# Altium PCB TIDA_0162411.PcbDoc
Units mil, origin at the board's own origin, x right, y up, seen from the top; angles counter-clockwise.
Board outline 1285 x 1080 mil, 2 copper layers (Top Layer, Bottom Layer), stack 4.4 mil thick; 24 components, 21 nets, 89 pads, 29 vias.
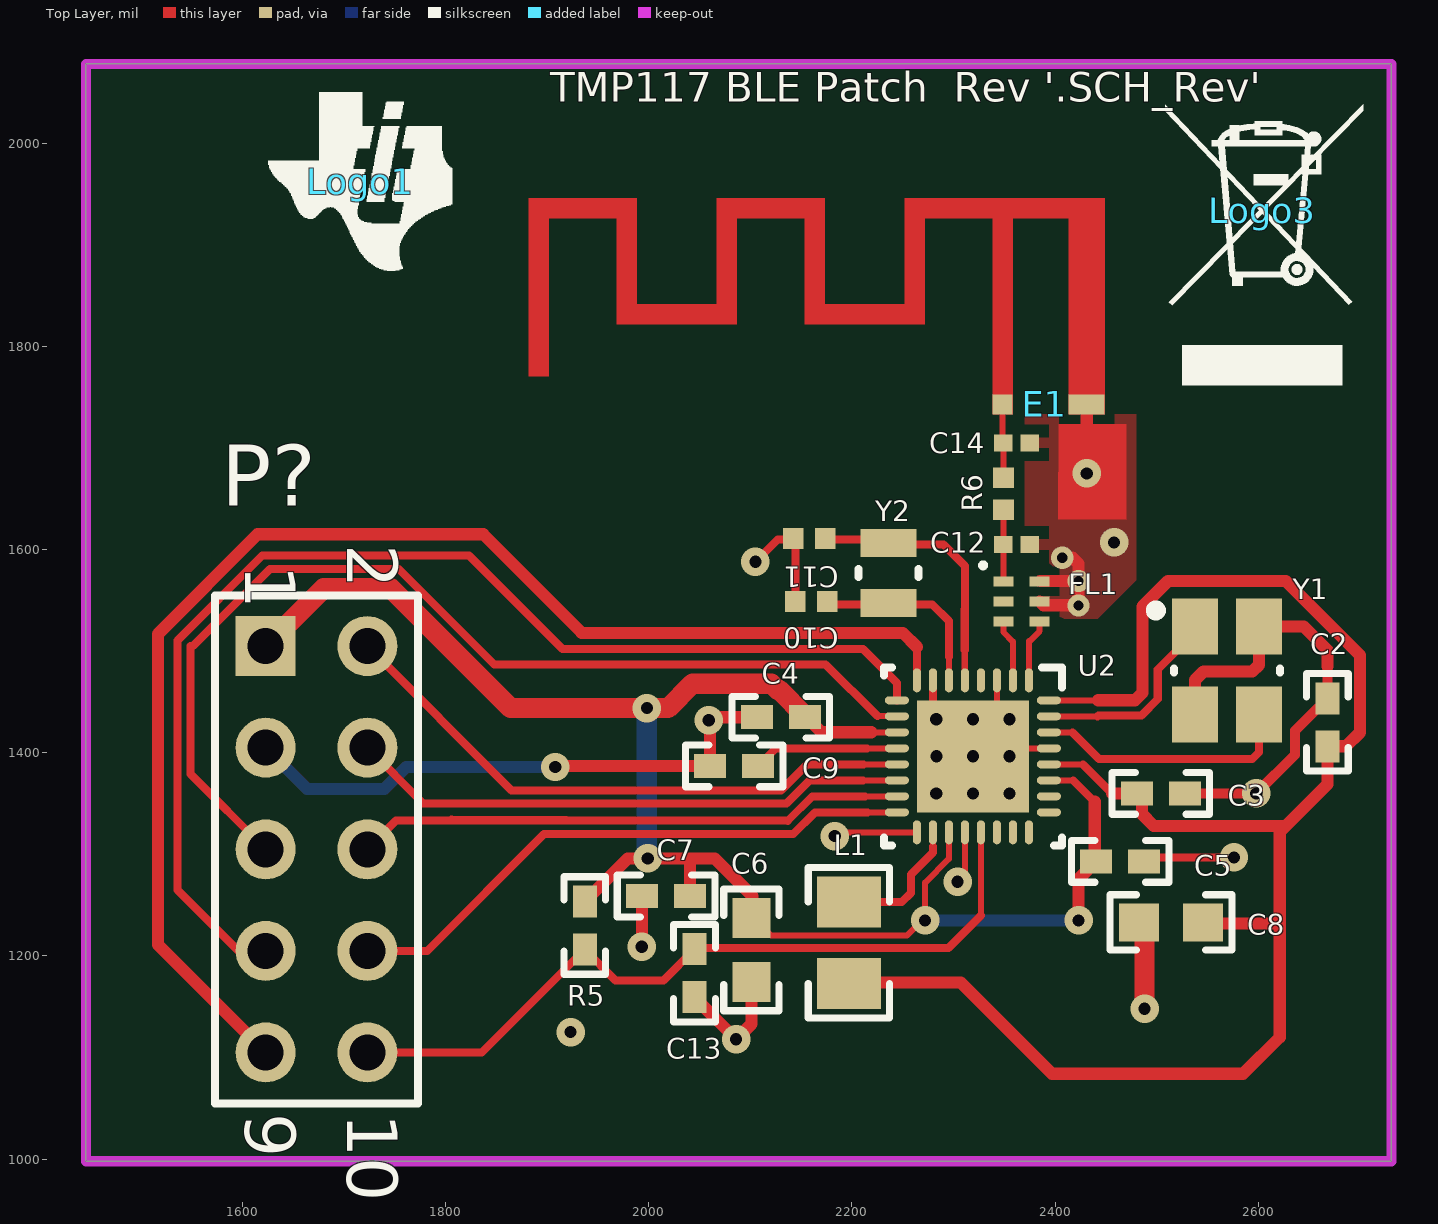
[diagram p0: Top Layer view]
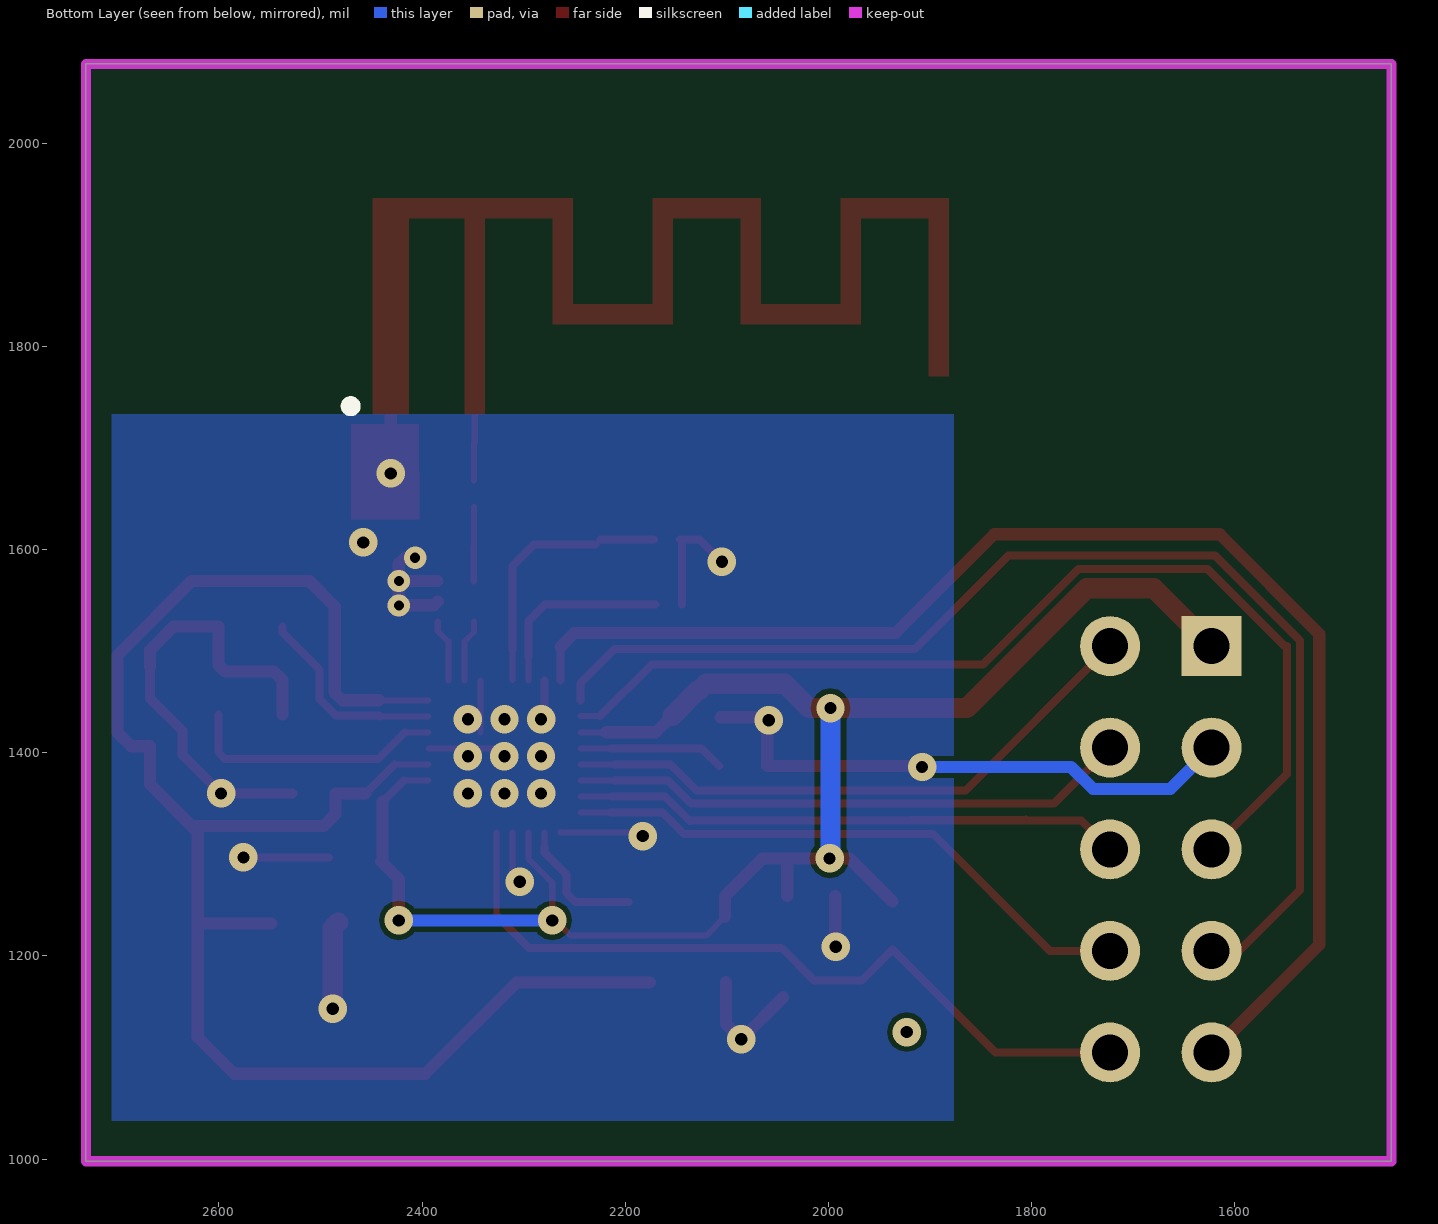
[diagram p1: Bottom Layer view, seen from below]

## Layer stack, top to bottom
Top Solder: solder mask 1, Polymide, Dk 3.3
Top Layer: signal copper 0.7
Dielectric1: core 3, Polymide, Dk 3.3
Bottom Layer: signal copper 0.7
Bottom Solder: solder mask 1, Polyimide, Dk 3.3

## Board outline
1446,998 1446,2078 2731,2078 2731,998

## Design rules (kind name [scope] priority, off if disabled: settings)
AcuteAngle [All] p1: minimum=4.50000000000000E+0001 checktracksonly=FALSE
AssemblyTestPointUsage [All] p1: valid=2
BoardOutlineClearance BoardOutlineClearance_MountingHoles [OnCopper and InComponentClass('Mounting Holes')] p1 off: gap=40
BoardOutlineClearance BoardOutlineClearance_Poly [OnCopper and IsPoly] p2: gap=25
BoardOutlineClearance [OnCopper and Not InComponentClass('Logo') and not InComponentClass('FiducialMark') and not InRegion(1000,500,4000,800) and not InPoly] p3 off: gap=40
Clearance Clearance_2 [InNamedPolygon('GND_L01_P002') vs InComponent('E1')] p1: gap=0
Clearance Clearance_Keepouts [((IsTrack Or IsArc) And Not InPoly) And IsFree and IsKeepOut vs ((IsTrack Or IsArc) And Not InPoly) And IsFree and IsKeepOut] p2: gap=0
Clearance Clearance_Poly [InPolygon] p3 off: gap=25
Clearance [All] p4: gap=5
ComponentClearance ComponentClearance_MountingHoles_FiducialMarks [InComponentClass('Mounting Holes') vs InComponentClass('FiducialMark')] p1: gap=50 collisioncheckmode=3 verticalgap=10 showdistances=FALSE
ComponentClearance ComponentClearance_Shunt [InComponentClass('Header') vs InComponentClass('Shunt')] p2: gap=0 collisioncheckmode=3 verticalgap=0 showdistances=FALSE
ComponentClearance ComponentClearance_Logo [InComponentClass('Logo')] p3: gap=50 collisioncheckmode=3 verticalgap=10 showdistances=FALSE
ComponentClearance ComponentClearance_ScrewToNut [(HasFootprint('NY PMS 440 0025 PH')) vs (HasFootprint('Keystone_1902C'))] p4: gap=5 collisioncheckmode=3 verticalgap=10 showdistances=FALSE
ComponentClearance ComponentClearance_MountingHoles [InComponentClass('Mounting Holes')] p5: gap=250 collisioncheckmode=3 verticalgap=100000 showdistances=FALSE
ComponentClearance ComponentClearance_SmallPassives [HasFootprint('0201*') or HasFootprint('0402*') or HasFootprint('0508') or HasFootprint('0603*') or HasFootprint('0612') or HasFootprint('0805*') or HasFootprint('0815*') or HasFootprint('0830*') or HasFootprint('1206*') or HasFootprint('1210*') or HasFootprint('1808*') or HasFootprint('1812*') or HasFootprint('1825*') or HasFootprint('2010*') or HasFootprint('2220*') or HasFootprint('2225*') or HasFootprint('2512*') or HasFootprint('2728*') or HasFootprint('3518*') vs HasFootprint('0201*') or HasFootprint('0402*') or HasFootprint('0508') or HasFootprint('0603*') or HasFootprint('0612') or HasFootprint('0805*') or HasFootprint('0815*') or HasFootprint('0830*') or HasFootprint('1206*') or HasFootprint('1210*') or HasFootprint('1808*') or HasFootprint('1812*') or HasFootprint('1825*') or HasFootprint('2010*') or HasFootprint('2220*') or HasFootprint('2225*') or HasFootprint('2512*') or HasFootprint('2728*') or HasFootprint('3518*')] p6: gap=14.96 collisioncheckmode=3 verticalgap=10 showdistances=FALSE
ComponentClearance ComponentClearance_THtoSMT [IsThruComponent vs IsSMTComponent] p7: gap=40 collisioncheckmode=3 verticalgap=30 showdistances=FALSE
ComponentClearance ComponentClearance_THtoTH [IsThruComponent vs IsThruComponent] p8: gap=15 collisioncheckmode=3 verticalgap=30 showdistances=FALSE
ComponentClearance [All] p9: gap=15 collisioncheckmode=3 verticalgap=10 showdistances=FALSE
DiffPairsRouting [All] p1: maxlimit=100 minlimit=10 mostfreqgap=10 toplayer_minwidth=15 toplayer_maxwidth=15 toplayer_prefwidth=15 bottomlayer_minwidth=15 bottomlayer_maxwidth=15 bottomlayer_prefwidth=15 maxuncoupledlength=1000
FabricationTestPointUsage TestPointUsage [All] p1: valid=2 allowmultiple=FALSE
FabricationTestpoint Testpoint [All] p1: side=3 testpointundercomponent=TRUE minsize=40 maxsize=100 preferedsize=60 minholesize=0 maxholesize=40 preferedholesize=32 testpointgrid=1 allowsidetop=TRUE allowsidebottom=TRUE usegrid=TRUE gridtolerance=0.01
FanoutControl Fanout_LCC [IsLCC] p1: bgadir=Out bgaviamode=Centered fanoutstyle=Auto fanoutdirection=Alternating viagrid=1 // Fanout_LCC (Default Rule)
FanoutControl Fanout_BGA [IsBGA] p2: bgadir=Out bgaviamode=Centered fanoutstyle=Auto fanoutdirection=Alternating viagrid=1 // Fanout_BGA (Default Rule)
FanoutControl Fanout_Default [All] p4: bgadir=Out bgaviamode=Centered fanoutstyle=Auto fanoutdirection=Alternating viagrid=1 // Fanout_Default (Default Rule)
FanoutControl Fanout_Small [(CompPinCount < 5)] p5: bgadir=Out bgaviamode=Centered fanoutstyle=Auto fanoutdirection=OutThenIn viagrid=1 // Fanout_Small (Default Rule)
HoleSize [All] p1: absolutevalues=TRUE maxlimit=251 minlimit=7.87 maxpercent=80.000 minpercent=20.000
MinimumAnnularRing MinimumAnnularRing_ThermalPadVias [IsVia and InAnyComponent] p1: minimumring=5.91
MinimumAnnularRing [All] p2: minimumring=5
MinimumSolderMaskSliver MinimumSolderMaskSliver_Logo [InComponentClass('Logo') vs InComponentClass('Logo')] p1: minsoldermaskwidth=0.7
MinimumSolderMaskSliver [All] p2: minsoldermaskwidth=2
PlaneClearance [All] p1: clearance=10
PlaneConnect [All] p1: planeconnectstyle=Direct reliefexpansion=10 reliefentries=4 reliefconductorwidth=10 reliefairgap=10
PolygonConnect [All] p1: connectstyle=Direct reliefconductorwidth=10 reliefentries=4 polygonreliefangle="45 Angle" airgapwidth=10
RoutingVias ThermalPadVias [IsVia and InAnyComponent] p1: holewidth=7.87 width=19.68 viastyle="Through Hole" minholewidth=7.87 minwidth=19.68 maxholewidth=12.99 maxwidth=23.62
RoutingVias [All] p2: holewidth=12 width=28 viastyle="Through Hole" minholewidth=7.9 minwidth=21.9 maxholewidth=40 maxwidth=65
ShortCircuit NoNet [IsComponentVia and not InAnyNet vs IsComponentPad and not InAnyNet] p1: allowed=TRUE
ShortCircuit [All] p2: allowed=FALSE
SilkToBoardRegionClearance [Not ((IsComment or IsDesignator) And (Hide <> 'False')) and not InRegion(1000,500,4000,800)] p1:
SilkToSilkClearance SilkToSilkClearance_Pb-FreeLogo [(HasFootprint('Pb-Free_Overlay_Medium') OR HasFootprint('Pb-Free_Overlay_Small')) vs (HasFootprint('Pb-Free_Overlay_Medium') OR HasFootprint('Pb-Free_Overlay_Small'))] p1: silktosilkclearance=0
SilkToSilkClearance [All] p2: silktosilkclearance=4
SilkToSolderMaskClearance "Silk to Solder Mask Opening" [All] p1: minsilkscreentomaskgap=1.5 clearancetoexposedcopper=FALSE
SolderMaskExpansion [All] p1: expansion=1.97
Width [All] p1: maxlimit=20 minlimit=4 preferedwidth=8 checkconnectedcopper=TRUE
13 further rules are at their usual default settings.

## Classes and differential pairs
component class Logo: Logo1

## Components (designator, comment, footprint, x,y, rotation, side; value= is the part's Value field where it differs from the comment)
C2 "GRM155R71E104KE14D" 0402 2668,1430 r270 top
C3 "GRM155R71E104KE14D" 0402 2504,1360 r180 top
C4 "GRM155R71E104KE14D" 0402 2130,1435 r0 top
C5 "GRM155R71E104KE14D" 0402 2464,1293 r180 top
C6 "C1608X5R1E106M080AC" 0603 2101,1206 r270 top
C7 "GRM155R71E104KE14D" 0402 2017,1259 r180 top
C8 "C1608X5R1E106M080AC" 0603 2514,1233 r180 top
C9 "GRM152R60J105ME15D" 0402 2084,1387 r0 top
C10 "GRM155R71E104KE14D" CAPC0402(1005)33_L 2160,1549 r0 top
C11 "GRM155R71E104KE14D" CAPC0402(1005)33_L 2158,1611 r0 top
C12 "DNP" 0201_033 2362,1605 r0 top
C13 "GRM155R71E104KE14D" 0402 2045,1183 r270 top
C14 "DNP" 0201_033 2362,1705 r0 top
E1 "ANTENNA_IIFA" ANTENNA_IIFA 2431,1733 r180 top net-tie
FL1 "2450BM14G0011" Johanson_2450BM14G0011 2367,1549 r0 top
L1 "CKS2125100M-T" 0805_HV 2197,1213 r270 top
Logo1 "Texas Instruments" TI_Symbol_Overlay_Small 1716,1962 r0 top
Logo3 "WEEE logo" WEEE_Minimum 2604,1934 r0 top
P? "Header 5X2" HDR2X5 1623,1505 r270 top
R5 "ERJ-2RKF1003X" 0402 1937,1230 r90 top
R6 "CRCW02010000Z0ED" CAPC0402(1005)33_L 2349,1655 r270 top
U2 "CC2640R2FRSMR" RSM0032B_NV 2319.05,1396.47 r270 top
Y1 "TSX-3225 24.0000MF15X-AC3" EPSON_TSX-3225 2569,1481 r0 top
Y2 "CM2012H32768DZFT" CM2012H 2236,1577 r90 top

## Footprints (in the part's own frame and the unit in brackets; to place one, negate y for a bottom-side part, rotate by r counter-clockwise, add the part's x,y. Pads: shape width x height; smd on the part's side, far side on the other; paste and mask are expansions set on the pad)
0201_033 [mm] "SMD, 2-Leads, Height 0.33mm"
  rect 0.46x0.42 smd mask+0.048: 1(-0.33,0) 2(0.33,0)
  body extent -0.31,-0.16 0.31,0.16, height 0.33
0402 [mm] "0402 from SM-752 data"
  rect 0.8x0.6 smd: 1(-0.6,0) 2(0.6,0)
  silkscreen extent -1.22,-0.52 1.22,0.52, body extent -0.55,-0.3 0.55,0.3, height 0.6
0603 [mm] "0603 from SM-752 data"
  rect 1x0.95 smd: 1(-0.8,0) 2(0.8,0)
  silkscreen extent -1.52,-0.69 1.52,0.69, body extent -0.87,-0.47 0.87,0.47, height 1
0805_HV [mil] "0805 with 30mil clearance between pads"
  rect 50x63 smd: 1(-40,0) 2(40,0)
  silkscreen extent -74,-40 74,40, body extent -43,-29 43,29, height 57
ANTENNA_IIFA [mm] "PCB Antenna, 2-Leads"
  rect 0.9x0.5 smd paste-1 mask-1: 1(0,-0.25)
  rect 0.5x0.5 smd paste-1 mask-1: 2(2.1,-0.25)
  Top Layer region: -0.45,0 -0.45,-5.4 4.55,-5.4 4.55,-2.76 6.55,-2.76 6.55,-5.4 9.25,-5.4 9.25,-2.76 11.25,-2.76 11.25,-5.4 13.95,-5.4 13.95,-0.96 13.45,-0.96 13.45,-4.9 11.75,-4.9 11.75,-2.26 8.75,-2.26 8.75,-4.9 7.05,-4.9 7.05,-2.26 4.05,-2.26 4.05,-4.9 2.35,-4.9 2.35,0 1.85,0 1.85,-4.9 0.45,-4.9 0.45,0
CAPC0402(1005)33_L [mm] "Chip Capacitor, Body 1.0x0.5mm, Height 0.33mm, IPC High Density"
  rect 0.52x0.52 smd: 1(0.4,0) 2(-0.4,0)
  body extent -0.55,-0.3 0.55,0.3, height 0.33
CM2012H [mm] "SMD, 2-Leads, Body 2.05x1.2mm"
  rect 0.7x1.4 smd: 1(-0.75,0) 2(0.75,0)
  silkscreen extent -0.1,-0.75 0.1,0.75, body extent -1.07,-0.65 1.07,0.65, height 0.6
EPSON_TSX-3225 [mm] "SMD, 4-Leads, Body 2.65x3.35mm, Height 0.6mm"
  rect 1.15x1.4 smd: 1(-0.8,1.1) 2(-0.8,-1.1) 3(0.8,-1.1) 4(0.8,1.1)
  silkscreen extent -1.9,-0.05 1.33,1.62, body extent -1.33,-1.68 1.33,1.68, height 0.61
HDR2X5 [mm] "Connector; Header; 5x2 Position"
  rect 1.5x1.5 hole 0.9: 1(0,0)
  round 1.5 hole 0.9: 2(0,2.54) 3(2.54,0) 4(2.54,2.54) 5(5.08,0) 6(5.08,2.54) 7(7.62,0) 8(7.62,2.54) 9(10.16,0) 10(10.16,2.54)
  silkscreen extent -1.27,-1.27 11.43,3.81
Johanson_2450BM14G0011 [mm] "SMD, 6-Leads, Body 1.6x0.8mm, Pitch 0.5mm"
  rect 0.5x0.25 smd: 1(-0.45,0.5) 2(-0.45,0) 3(-0.45,-0.5) 4(0.45,-0.5) 5(0.45,0) 6(0.45,0.5)
  silkscreen extent -1.02,0.84 -0.9,0.96, body extent -0.45,-0.85 0.45,0.85, height 0.71
RSM0032B_NV [mm] "QFN, 32-Leads, Body 4x4mm, Pitch 0.4mm, Thermal Pad 2.8x2.8mm, TI Recommended"
  oval 0.6x0.2 smd: 1(-1.9,1.4) 2(-1.9,1) 3(-1.9,0.6) 4(-1.9,0.2) 5(-1.9,-0.2) 6(-1.9,-0.6) 7(-1.9,-1) 8(-1.9,-1.4) 17(1.9,-1.4) 18(1.9,-1) 19(1.9,-0.6) 20(1.9,-0.2) 21(1.9,0.2) 22(1.9,0.6) 23(1.9,1) 24(1.9,1.4)
  oval 0.2x0.6 smd: 9(-1.4,-1.9) 10(-1,-1.9) 11(-0.6,-1.9) 12(-0.2,-1.9) 13(0.2,-1.9) 14(0.6,-1.9) 15(1,-1.9) 16(1.4,-1.9) 25(1.4,1.9) 26(1,1.9) 27(0.6,1.9) 28(0.2,1.9) 29(-0.2,1.9) 30(-0.6,1.9) 31(-1,1.9) 32(-1.4,1.9)
  rect 2.8x2.8 smd paste-1.4: 33(0,0)
  silkscreen extent -2.23,-2.23 2.23,2.23, body extent -2.07,-2.07 2.08,2.08, height 1.01
TI_Symbol_Overlay_Small [mil]
  silkscreen extent -90,-88 91,88
WEEE_Minimum [mil] "WEEElie bin"
  silkscreen extent -95,-172 99,104

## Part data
C2 C3 C4 C5 C7 C13: library part CMP-0006659-2, "CAP, CERM, 0.1 uF, 25 V, +/- 10%, X7R, 0402"
C6 C8: library part CMP-0007007-5, "CAP, CERM, 10 uF, 25 V, +/- 20%, X5R, 0603"
C9: library part CMP-0006372-2, "CAP, CERM, 1 uF, 6.3 V, +/- 20%, X5R, 0402"
C10 C11: library part CMP-0006659-2, "CAP, CERM, 12 pF, 50 V, +/- 5%, C0G/NP0, 0201"
C12 C14: library part CMP-0009654-3, "CAP, CERM, 470 pF, 50 V, +/- 10%, X7R, AEC-Q200 Grade 1, 0201"
E1: library part CMP-0001736-1, "PCB Antenna.  There is nothing to buy or mount."
FL1: library part CMP-0001890-2, "2.4GHz Impedance Matched Balun + embedded FCC/ETSI Band Pass Filter, SMD"
L1: library part CMP-0059606-1, "Inductor, Multilayer, Ferrite, 10 uH, 0.11 A, 0.52 ohm, SMD"
Logo1: library part CMP-0074838-1, "Texas Instrument Corporate Signature"
Logo3: library part CMP-0074769-1
P?: "Header, 5-Pin, Dual row"
R5: library part CMP-0026659-1, "RES, 100 k, 1%, 0.1 W, 0402"
R6: library part CMP-0027008-4, "RES, 0, 5%, 0.05 W, 0201"
U2: library part CMP-0076686-1, "SimpleLink(TM) Bluetooth(R) low energy Wireless MCU, RSM0032B (VQFN-32)"
Y1: library part CMP-0079304-1, "Crystal, 24 MHz, 10 ppm, 9 pF, SMD"
Y2: library part CMP-0004654-3, "Crystal, 32.768 kHz, SMD"

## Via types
v1: diameter 28, hole 12, Top Layer to Bottom Layer, tented both sides, 15 vias
v2: diameter 28, hole 12, Top Layer to Bottom Layer, tented bottom, 11 vias
v3: diameter 22, hole 10, Top Layer to Bottom Layer, tented both sides, 3 vias

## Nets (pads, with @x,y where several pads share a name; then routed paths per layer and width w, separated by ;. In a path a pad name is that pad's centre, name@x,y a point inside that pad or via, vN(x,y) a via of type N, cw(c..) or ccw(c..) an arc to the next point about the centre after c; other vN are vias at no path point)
DCDC_SW: L1.1 U2.18 | length 133.4
  Top Layer w6: 2279.68,1307.68 U2.18
  Top Layer w8: L1.1 2249,1253 2258,1262 2258,1280 2279.68,1301.68 2279.68,1307.68
GND: C2.1 C3.1 C4.1 C5.1 C6.2 C7.2 C8.2 C9.1 C10.2 C11.2 C12.2 C13.2 C14.2 E1.1 FL1.5 FL1.6 P?.3 U2.3 U2.7 U2.17 U2.20 U2.29 U2.33 Y1.2 Y1.4 | length 1922
  Top Layer w6: v1(2183,1318) 2186.67,1321.67 U2.17 U2.17@2264.06,1321.79 ; v1(2304,1273) 2311.18,1280.18 U2.20 ; U2.33@2326.93,1404.34 U2.29 ; U2.33@2342.68,1420.09 U2.3
  Top Layer w8: v1(2105,1588) 2127,1610 C11.2@2146.01,1610 ; C10.2@2144.38,1546.04 C11.2@2144.38,1608.37 ; U2.33@2279.68,1435.84 U2.7 ; C5.1@2491.62,1297 v1(2576,1297)
  Top Layer w10: C3.1 v1(2598,1360) 2636,1398 2636,1421.62 C2.1 2668,1485
  Top Layer w12: v2(1908,1386) 1909,1387 C9.1 v1@2060.38,1430.62 ; v1@1993.38,1209.38 C7.2 ; C13.2 2045,1159 v1(2086,1118) 2101,1133 C6.2 ; v1@2064.76,1435 C4.1 ; FL1.5 2388.48,1545.24 2422.76,1545.24 v3(2423,1545) v3(2423,1569) ; FL1.6@2385.03,1569 v3(2423,1569) ; v3(2407,1592) 2417,1592 2423,1586 v3(2423,1569) ; 2431,1708 E1.1 ; Y1.2 2537.5,1471.5 2546,1480 2594,1480 2600.5,1486.5 Y1.4 2644.69,1524.31 2668,1501 2668,1485
  Top Layer w20: C8.2 2488,1227.5 v1(2488,1148)
  Bottom Layer w12: P?.3 1663.53,1364.47 1739.79,1364.47 1761.31,1386 v2(1908,1386)
  other v1: 1993,1209 2059,1432 2458,1607
  other v2: 2283,1360 2319,1360 2355,1360 2283.05,1396.47 2319.05,1396.47 2355.05,1396.47 2283,1433 2319,1433 2355,1433 2431,1675
JTAG_RST: C13.1 P?.10 R5.1 U2.21 | length 764.8
  Top Layer w6: 2326.93,1239.93 U2.21
  Top Layer w8: P?.10 1835.62,1105 R5.1 1967.38,1176 2014.38,1176 C13.1 ; C13.1@2046.38,1208 2295,1208 2326.93,1239.93
JTAG_TCKC: P?.4 U2.14 | length 553.5
  Top Layer w6: 2210.85,1372.85 U2.14
  Top Layer w8: P?.4 1778,1350 2135.38,1350 2158.23,1372.85 2210.85,1372.85
JTAG_TDI: P?.8 U2.16 | length 577.7
  Top Layer w6: 2215.35,1341.35 U2.16@2244.25,1341.35
  Top Layer w8: P?.8 1781.96,1205 1897,1320.04 2142.19,1320.04 2163.5,1341.35 2215.35,1341.35
JTAG_TDO: P?.6 U2.15 | length 771
  Top Layer w6: 2212.9,1357.1 U2.15
  Top Layer w8: P?.6 1751.34,1333.34 2033.99,1333.34 ; 1806,1334 2033.99,1333.34 ; 2212.9,1357.1 2160.87,1357.1 2136.81,1333.04 2033.99,1333.34
JTAG_TMSC: P?.2 U2.13 | length 711.7
  Top Layer w6: 2211.41,1388.59 U2.13
  Top Layer w8: P?.2 1865,1363 ; 1986,1363 1865,1363 ; 2211.41,1388.59 2155.59,1388.59 2130,1363 1865,1363
NetC9_2: C9.2 U2.12 | length 143.8
  Top Layer w6: 2214.66,1404.34 U2.12
  Top Layer w8: C9.2 2124.96,1404.34 2214.66,1404.34
NetC12_1: C12.1 FL1.1 R6.1 | length 72
  Top Layer w6: C12.1 R6.1@2349.01,1642 ; FL1.1 C12.1@2349.28,1603.72
NetC14_1: C14.1 E1.2 R6.2 | length 74.2
  Top Layer w6: C14.1@2348.32,1705.68 E1.2 ; R6.2@2349,1667.99 C14.1
RF_N: FL1.3 U2.2 | length 62.1
  Top Layer w4: FL1.3@2349,1529.03 FL1.3
  Top Layer w6: FL1.3@2349,1529.03 2349,1518.85 2358.42,1509.42 U2.2
RF_P: FL1.4 U2.1 | length 62.8
  Top Layer w4: 2374.17,1509.83 2374.83,1509.83
  Top Layer w6: U2.1 2374.17,1509.83 ; 2374.83,1509.83 2384.72,1519.72 FL1.4
SCL: P?.7 U2.9 | length 1169.1
  Top Layer w8: P?.7 1596,1205 1536,1265 1536,1510.38 1619.62,1594 1823,1594 1915,1502 2210.84,1502 2244.25,1468.59 U2.9
SDA: P?.5 U2.10 | length 1017.3
  Top Layer w6: 2224.99,1436 U2.10@2244.09,1436
  Top Layer w8: P?.5 1549,1379 1549,1505 1551.22,1505 1627.22,1581 1753.87,1581 1847.87,1487 2004,1487 2173.99,1487 2224.99,1436
V+: P?.9 U2.8 | length 1331.9
  Top Layer w8: U2.8 U2.8@2263.94,1481.06 ; U2.8@2264,1471.34 2264,1504
  Top Layer w12: P?.9 1517,1211 1517,1517 1615,1615 1837,1615 1934,1518 2250,1518 2264,1504
VCC: C4.2 C5.2 C6.1 C7.1 P?.1 R5.2 U2.11 U2.19 U2.27 | length 1727.3
  Top Layer w6: C6.1@2102,1238.5 2120.5,1220 2254,1220 v1@2269,1235 ; 2218.91,1420.09 U2.11 ; v1(2272,1235) 2272,1272.11 2295.43,1295.54 U2.19 ; U2.27 2417.85,1372.85
  Top Layer w8: 2417.85,1372.85 2439,1351.69
  Top Layer w12: R5.2 1979.38,1296 v1(1999,1296) 2065,1296 2102,1259 C6.1@2102,1238.5 ; C7.1 2040.62,1292.62 ; C4.2@2153.62,1436.53 2170.06,1420.09 2218.91,1420.09 ; v1(2423,1235) 2423,1275.62 C5.2 ; C5.2@2439,1294.38 2439,1351.69
  Top Layer w20: P?.1 1680,1562 1746,1562 1864,1444 v1(1998.15,1444) 2019,1444 2043,1468 2120.62,1468 2126.81,1461.81 2128.34,1461.81 C4.2@2153.62,1436.53
  Bottom Layer w12: v1(2272,1235) v1(2423,1235)
  Bottom Layer w20: v1@1998.15,1296.85 v1(1998.15,1444)
VDDR: C2.2 C3.2 C8.1 L1.2 U2.28 U2.32 | length 1695.3
  Top Layer w6: U2.28 2427.41,1388.59 ; U2.32 2442.41,1451.59
  Top Layer w8: 2427.41,1388.59 2456,1360
  Top Layer w12: L1.2@2176,1174 2307,1174 2397,1084 2585,1084 2621,1120 2621,1232 ; 2442.41,1451.59 2478.59,1451.59 2486,1459 2486,1544 2511,1569 2627,1569 2700,1496 2700,1420 2686.38,1406.38 C2.2 2668,1369 2627,1328 ; 2456,1360 2485.38,1360 2485.38,1339.62 2497,1328 2627,1328 ; C8.1@2548.5,1232 2621,1232 ; 2621,1232 2621,1324 2623,1324 2627,1328
X24M_N: U2.30 Y1.3 | length 257.2
  Top Layer w6: U2.30@2393.95,1420 2417.21,1420
  Top Layer w8: 2417.21,1420 2443.21,1394 2594,1394 2600.5,1400.5 Y1.3
X24M_P: U2.31 Y1.1 | length 200.8
  Top Layer w6: U2.31 2441.84,1435.84
  Top Layer w8: 2441.84,1435.84 2442.59,1436.59 2484.8,1436.59 2501,1452.79 2501,1482 2537.5,1518.5 Y1.1
X32K_Q1: C11.1 U2.5 Y2.2 | length 255.4
  Top Layer w6: U2.5@2311,1471.45 2311,1501
  Top Layer w8: C11.1@2171.99,1610 Y2.2@2224.4,1610 ; Y2.2@2229.37,1605.03 2289.97,1605.03 2311.18,1583.82 2311,1501
X32K_Q2: C10.1 U2.6 Y2.1 | length 190.1
  Top Layer w6: U2.6 2295.43,1494.43
  Top Layer w8: C10.1@2170.36,1546.04 Y2.1@2229.3,1546.04 ; Y2.1@2229.37,1545.97 2279.03,1545.97 2295.43,1529.57 2295.43,1494.43
pads on no net: FL1.2 U2.4 U2.22 U2.23 U2.24 U2.25 U2.26
copper on no net:
  other v1: 1923,1125

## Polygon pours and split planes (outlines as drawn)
GND on Bottom Layer "Bottom Layer-GND" (solid, pour order 2): 1877,1733 2707,1733 2707,1038 1877,1038
GND on Top Layer "Top Layer-No Net" (solid, pour order 6): 2372,1733 2370,1731 2370,1532 2442,1532 2480,1570 2480,1733

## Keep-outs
Keep-Out Layer:
  lines w10: 1446,998 2731,998 2731,2078 1667,2078 1446,2078 1446,998

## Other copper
Top Layer:
  region net GND: 2403.28,1723.27 2469.73,1723.27 2470,1723 2470,1630 2403,1630
  pour cut-out: 2669.38,1572.25 ccw(c3046.08,2027.34) 2669.38,1572.25 ccw(c-377.8,-2305.68)

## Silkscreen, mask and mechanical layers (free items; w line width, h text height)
Top Overlay:
  text "TMP117 BLE Patch  Rev '.SCH_Rev'" at 1903,2031 h50
M9 Title Sheet:
  lines w10: -491.5,1041.5 -291.5,1041.5 ; -491.5,3416.5 -291.5,3416.5 ; -491.5,5791.5 -291.5,5791.5 ; 2008.5,7966.5 2008.5,8166.5 ; 4508.5,7966.5 4508.5,8166.5 ; 7008.5,7966.5 7008.5,8166.5 ; 9508.5,7966.5 9508.5,8166.5 ; 12008.5,7966.5 12008.5,8166.5 ; -491.5,-1333.5 14508.5,-1333.5 14508.5,8166.5 -491.5,8166.5 -491.5,-1333.5 ; -291.5,-1133.5 14308.5,-1133.5 14308.5,7966.5 -291.5,7966.5 -291.5,-1133.5
  text "1" at 739.84,8036.5 h70
  text "2" at 3235.5,8036.5 h70
  text "3" at 5724.84,8036.5 h70
  text "4" at 8231.51,8036.5 h70
  text "5" at 10730.5,8036.5 h70
  text "6" at 13235.5,8036.5 h70
  text "A" at -416.5,6893.5 h70
  text "A" at 14383.5,6893.5 h70
  text "B" at -416.5,4513.5 h70
  text "C" at -416.5,2138.5 h70
Mechanical 17:
  text ".Layer_Name" at 577,-858.49 h60
Mechanical 18:
  text ".Layer_Name" at 577,-858.49 h60
Mechanical 19:
  text ".Layer_Name" at 577,-858.49 h60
